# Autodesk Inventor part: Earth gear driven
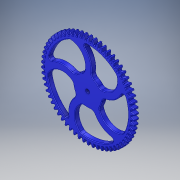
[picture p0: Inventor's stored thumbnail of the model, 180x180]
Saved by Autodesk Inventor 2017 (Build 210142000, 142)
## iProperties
Created: 2016-05
Part Number: Earth gear driven
Material: Generic
Document SubType Name: Modeling
Designer: Stan
Density: 1 g/cm^3
Appearance: Blue - Wall Paint - Glossy
Author: Stan
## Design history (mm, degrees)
sketch "Sketch1"
  geometry: A1 r 24.865 centre (-32.251, 47.242) between (-9.529, 57.341) and (-11.809, 61.398); A2 r 24.865 centre (-32.251, 47.242) between (-9.529, 57.341) and (-11.809, 61.398); A3 r 24.865 centre (16.63, 54.73) between (-7.113, 62.117) and (-8.074, 57.564); A4 r 24.865 centre (16.63, 54.73) between (-7.113, 62.117) and (-8.074, 57.564); A5 r 24.865 centre (-36.865, 43.737) between (-15.281, 56.082) and (-17.96, 59.888); A6 r 24.865 centre (-36.865, 43.737) between (-15.281, 56.082) and (-17.96, 59.888); A7 r 24.865 centre (11.007, 56.132) between (-13.361, 61.079) and (-13.856, 56.451); A8 r 24.865 centre (11.007, 56.132) between (-13.361, 61.079) and (-13.856, 56.451); A9 r 24.865 centre (-41.101, 39.783) between (-20.877, 54.249) and (-23.927, 57.764); A10 r 24.865 centre (-41.101, 39.783) between (-20.877, 54.249) and (-23.927, 57.764); A11 r 24.865 centre (5.272, 56.957) between (-19.471, 59.414) and (-19.496, 54.76); A12 r 24.865 centre (5.272, 56.957) between (-19.471, 59.414) and (-19.496, 54.76); A13 r 24.865 centre (-44.914, 35.42) between (-26.258, 51.858) and (-29.648, 55.047); A14 r 24.865 centre (-44.914, 35.42) between (-26.258, 51.858) and (-29.648, 55.047); A15 r 24.865 centre (-0.517, 57.198) between (-25.382, 57.139) and (-24.936, 52.507); A16 r 24.865 centre (-0.517, 57.198) between (-25.382, 57.139) and (-24.936, 52.507); A17 r 24.865 centre (-48.267, 30.695) between (-31.369, 48.936) and (-35.065, 51.765); A18 r 24.865 centre (-48.267, 30.695) between (-31.369, 48.936) and (-35.065, 51.765); A19 r 24.865 centre (-6.301, 56.852) between (-31.033, 54.278) and (-30.12, 49.715); A20 r 24.865 centre (-6.301, 56.852) between (-31.033, 54.278) and (-30.12, 49.715); A21 r 24.865 centre (-51.125, 25.654) between (-36.159, 45.511) and (-40.122, 47.952); A22 r 24.865 centre (-51.125, 25.654) between (-36.159, 45.511) and (-40.122, 47.952); A23 r 24.865 centre (-12.021, 55.923) between (-36.365, 50.86) and (-34.995, 46.412); A24 r 24.865 centre (-12.021, 55.923) between (-36.365, 50.86) and (-34.995, 46.412); A25 r 24.865 centre (-53.458, 20.35) between (-40.578, 41.619) and (-44.767, 43.647); A26 r 24.865 centre (-53.458, 20.35) between (-40.578, 41.619) and (-44.767, 43.647); A27 r 24.865 centre (-17.617, 54.42) between (-41.323, 46.92) and (-39.511, 42.634); A28 r 24.865 centre (-17.617, 54.42) between (-41.323, 46.92) and (-39.511, 42.634); A29 r 24.865 centre (-55.243, 14.838) between (-44.58, 37.301) and (-48.953, 38.894); A30 r 24.865 centre (-55.243, 14.838) between (-44.58, 37.301) and (-48.953, 38.894); A31 r 24.865 centre (-23.032, 52.359) between (-45.858, 42.499) and (-43.621, 38.418); A32 r 24.865 centre (-23.032, 52.359) between (-45.858, 42.499) and (-43.621, 38.418); A33 r 24.865 centre (-56.46, 9.173) between (-48.125, 32.599) and (-52.637, 33.742); A34 r 24.865 centre (-56.46, 9.173) between (-48.125, 32.599) and (-52.637, 33.742); A35 r 24.865 centre (-28.211, 49.76) between (-49.923, 37.641) and (-47.284, 33.808); A36 r 24.865 centre (-28.211, 49.76) between (-49.923, 37.641) and (-47.284, 33.808); A37 r 24.865 centre (-57.099, 3.414) between (-51.176, 27.563) and (-55.78, 28.244); A38 r 24.865 centre (-57.099, 3.414) between (-51.176, 27.563) and (-55.78, 28.244); A39 r 24.865 centre (-33.1, 46.651) between (-53.475, 32.398) and (-50.462, 28.851); A40 r 24.865 centre (-33.1, 46.651) between (-53.475, 32.398) and (-50.462, 28.851); A41 r 24.865 centre (-57.151, -2.38) between (-53.702, 22.244) and (-58.351, 22.456); A42 r 24.865 centre (-57.151, -2.38) between (-53.702, 22.244) and (-58.351, 22.456); A43 r 24.865 centre (-37.65, 43.063) between (-56.478, 26.822) and (-53.122, 23.597); A44 r 24.865 centre (-37.65, 43.063) between (-56.478, 26.822) and (-53.122, 23.597); A45 r 24.865 centre (-56.617, -8.15) between (-55.677, 16.697) and (-60.324, 16.437); A46 r 24.865 centre (-56.617, -8.15) between (-55.677, 16.697) and (-60.324, 16.437); A47 r 24.865 centre (-41.813, 39.033) between (-58.902, 20.97) and (-55.236, 18.102); A48 r 24.865 centre (-41.813, 39.033) between (-58.902, 20.97) and (-55.236, 18.102); A49 r 24.865 centre (-55.502, -13.836) between (-57.081, 10.979) and (-61.677, 10.25); A50 r 24.865 centre (-55.502, -13.836) between (-57.081, 10.979) and (-61.677, 10.25); A51 r 24.865 centre (-45.548, 34.602) between (-60.721, 14.904) and (-56.784, 12.421); A52 r 24.865 centre (-45.548, 34.602) between (-60.721, 14.904) and (-56.784, 12.421); A53 r 24.865 centre (-53.817, -19.38) between (-57.899, 5.148) and (-62.398, 3.957); A54 r 24.865 centre (-53.817, -19.38) between (-57.899, 5.148) and (-62.398, 3.957); A55 r 24.865 centre (-48.815, 29.817) between (-61.917, 8.684) and (-57.75, 6.613); A56 r 24.865 centre (-48.815, 29.817) between (-61.917, 8.684) and (-57.75, 6.613); A57 r 24.865 centre (-51.581, -24.725) between (-58.122, -0.736) and (-62.478, -2.376); A58 r 24.865 centre (-51.581, -24.725) between (-58.122, -0.736) and (-62.478, -2.376); A59 r 24.865 centre (-51.581, 24.725) between (-62.478, 2.376) and (-58.122, 0.736); A60 r 24.865 centre (-51.581, 24.725) between (-62.478, 2.376) and (-58.122, 0.736); A61 r 24.865 centre (-48.815, -29.817) between (-57.75, -6.613) and (-61.917, -8.684); A62 r 24.865 centre (-48.815, -29.817) between (-57.75, -6.613) and (-61.917, -8.684); A63 r 24.865 centre (-53.817, 19.38) between (-62.398, -3.957) and (-57.899, -5.148); A64 r 24.865 centre (-53.817, 19.38) between (-62.398, -3.957) and (-57.899, -5.148)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
  constraints: 992 point on circle, 496 centre point, 8 horizontal alignment, 8 vertical alignment, 1472 other
extrude "Extrusion1" new body sketch "Sketch1" distance "d2" = 6.35; taper "d3" = 0 deg
sketch "Sketch2" dims "d5" = 31.75
  geometry: L1 (0, 53.975)-(0, -15.875); A1 r 21.065 centre (-24.538, 27.292) between (-5.519, 18.233) and (-23.991, 48.35); A2 r 29.845 centre (-24.538, 27.292) between (4.02, 18.621) and (-9.581, 53.118); A3 r 29.845 centre (-33.538, -14.903) between (-16.468, 9.577) and (-53.479, 7.302); A4 r 21.065 centre (-33.538, -14.903) between (-19.046, 0.385) and (-53.397, -7.876); A5 r 29.845 centre (3.81, -36.502) between (-14.197, -12.702) and (-23.471, -48.605); A6 r 21.065 centre (3.81, -36.502) between (-6.252, -17.995) and (-9.01, -53.218); A7 r 29.845 centre (35.893, -7.656) between (7.693, -17.427) and (38.973, -37.342); A8 r 21.065 centre (35.893, -7.656) between (15.182, -11.506) and (47.829, -25.014); A9 r 29.845 centre (18.373, 31.77) between (18.952, 1.931) and (47.557, 25.526); A10 r 21.065 centre (18.373, 31.77) between (15.635, 10.884) and (38.57, 37.758); A11 r 53.975 centre (0, 0) between (-23.991, 48.35) and (-53.479, 7.302); A12 r 53.975 centre (0, 0) between (38.57, 37.758) and (-9.581, 53.118); A13 r 53.975 centre (0, 0) between (47.829, -25.014) and (47.557, 25.526); A14 r 53.975 centre (0, 0) between (-53.397, -7.876) and (-23.471, -48.605); A15 r 53.975 centre (0, 0) between (-9.01, -53.218) and (38.973, -37.342); A16 r 19.05 centre (0, 0) between (-5.519, 18.233) and (-16.468, 9.577); A17 r 19.05 centre (0, 0) between (-19.046, 0.385) and (-14.197, -12.702); A18 r 19.05 centre (0, 0) between (-6.252, -17.995) and (7.693, -17.427); A19 r 19.05 centre (0, 0) between (15.182, -11.506) and (18.952, 1.931); A20 r 19.05 centre (0, 0) between (15.635, 10.884) and (4.02, 18.621); 2 further points
  constraints: 41 point on circle, 20 centre point, 3 coincident, 2 end point, 1 vertical, 1 vertical alignment, 38 other
  dimensions: "d9" = 360 deg dimension on point (0, 0) A1.centre (derived)
extrude "Extrusion2" cut sketch "Sketch2" distance "d11" = 6.35; taper "d12" = 0 deg
sketch "Sketch3"
  geometry: C1 r 2.794 at (0, 0); 1 further point
  constraints: 1 centre point, 1 coincident
  dimensions: "d13" = 5.588 diameter of C1
extrude "Extrusion3" cut sketch "Sketch3" distance "d14" = 6.35; taper "d15" = 0 deg
fillet "Fillet1" dims "d16" = 3.175
fillet "Fillet2" dims "d17" = 6.35
fillet "Fillet3" dims "d18" = 6.35
fillet "Fillet4" dims "d19" = 0.79375
fillet "Fillet5" dims "d20" = 0.79375
fillet "Fillet6" dims "d21" = 0.79375
fillet "Fillet7" dims "d22" = 0.79375
fillet "Fillet8" dims "d23" = 0.79375
fillet "Fillet9" dims "d24" = 0.79375
fillet "Fillet10" dims "d25" = 0.79375
body "Solid1"
other parameters: "d4" = 107.95, "d6" = 38.1
